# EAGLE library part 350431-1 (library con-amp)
Universal MATE-N-LOK .250" Centerline, 600 V, 19 - 36 A max Source: http://catalog.tycoelectronics.com/ .. ENG_CD_350431_Y.pdf
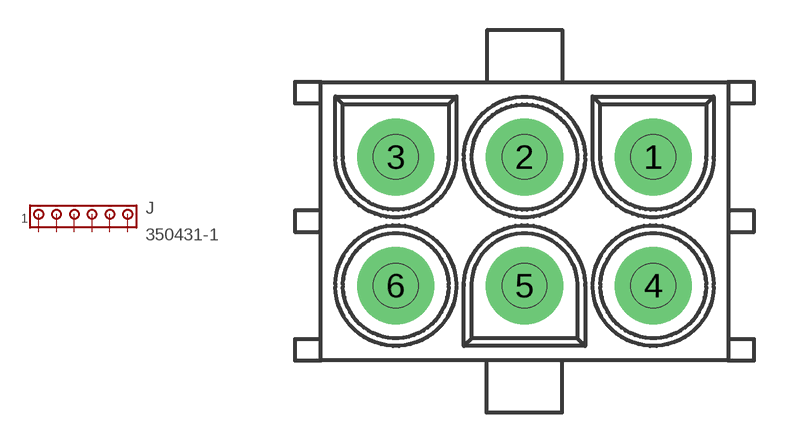
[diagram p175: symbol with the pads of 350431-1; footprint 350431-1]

Designator prefix J

## 350431-1 (MF: TYCO ELECTRONICS; MPN: 350431-1; OC_FARNELL: 285341; OC_NEWARK: 46F2054)  [350431-1]
1  1  pas
2  2  pas
3  3  pas
4  4  pas
5  5  pas
6  6  pas

## Footprint 350431-1 (pad centres in mm)
Universal MATE-N-LOK .250" Centerline, 600 V, 19 - 36 A max Source: http://catalog.tycoelectronics.com/ .. ENG_CD_350431_Y.pdf
drill 1.8 pad 3.81 round: 1 6.35,0; 2 0,0; 3 -6.35,0; 4 6.35,-6.35; 5 0,-6.35; 6 -6.35,-6.35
